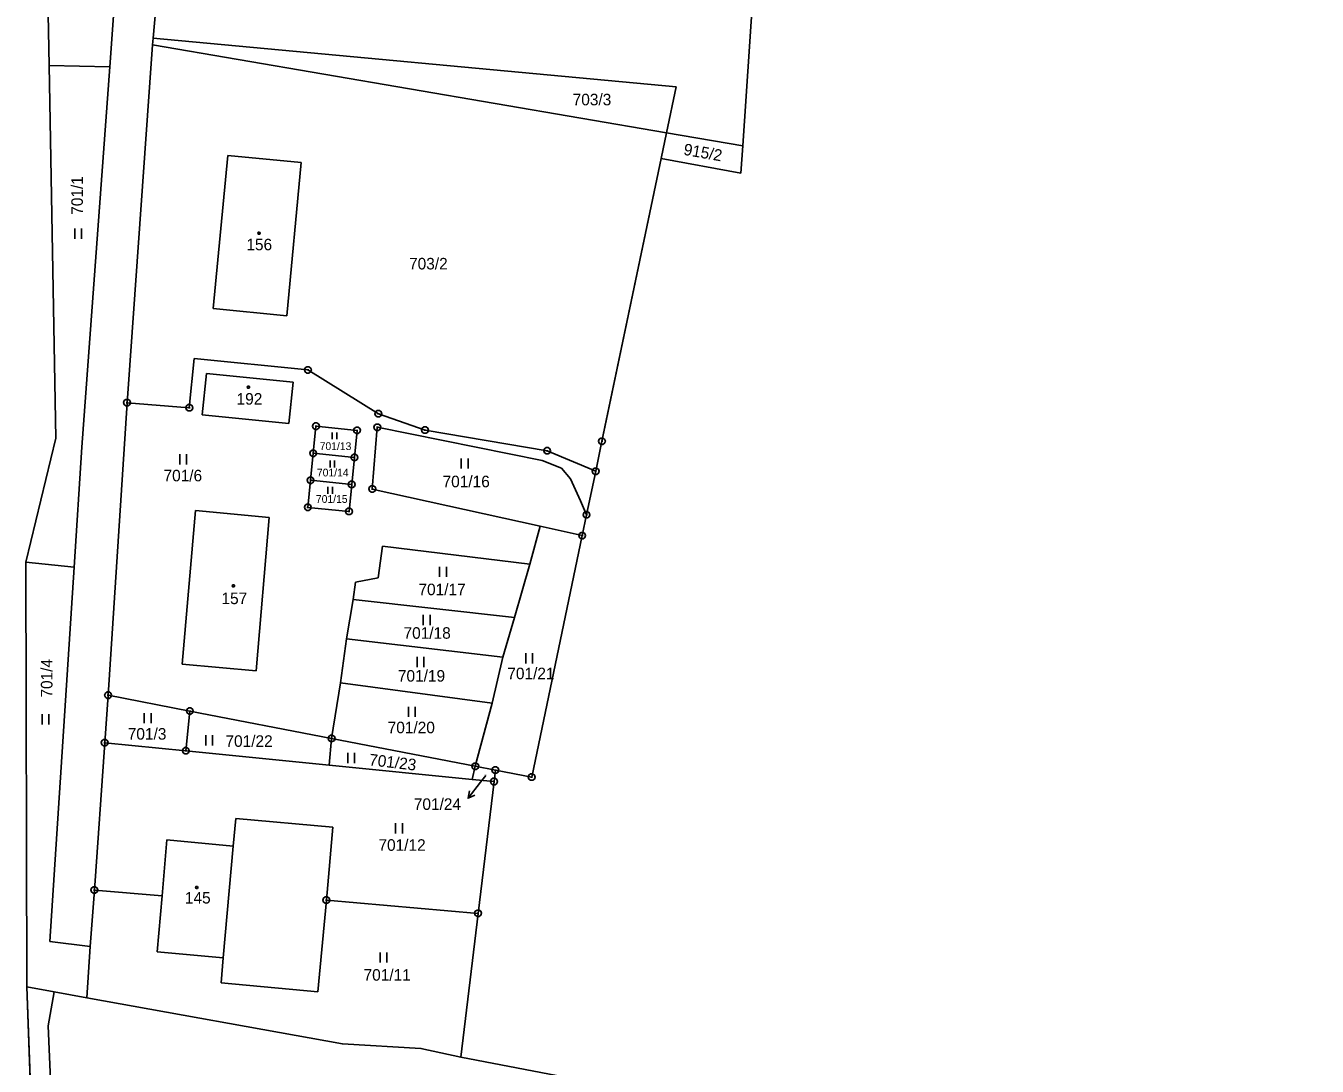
# Model space of a CAD drawing. Extents: x -580551 to -575069, y -1073031 to -1067931.
# Drawn here: x -578371.4 to -578181.2, y -1071127.8 to -1070974.7 of the extents above; entities that cross this region are included whole.
import ezdxf

# ---------------------------------------------------------------- set-up
doc = ezdxf.new("R2010")
doc.units = 0
for name, color, linetype in [('Druh pozemku', 7, 'Continuous'), ('Geodetické body', 7, 'Continuous'), ('Parcela', 7, 'Continuous'), ('Parcelní číslo', 7, 'Continuous'), ('Parcelní číslo_stavba', 7, 'Continuous'), ('Pomocná vrstva', 7, 'Continuous'), ('SR - hranice státu', 7, 'Continuous'), ('Vnitřní kresba', 7, 'Continuous')]:
    doc.layers.add(name, color=color, linetype=linetype)

msp = doc.modelspace()

# ---------------------------------------------------------------- linework, layer by layer
at = {"layer": 'Druh pozemku'}
for p, q in [((-578364.21, -1071004.53), (-578364.21, -1071006.03)), ((-578363.21, -1071006.03), (-578363.21, -1071004.53)), ((-578326.305, -1071034.525), (-578326.305, -1071035.53)), ((-578325.635, -1071035.53), (-578325.635, -1071034.525)), ((-578348.77, -1071037.74), (-578348.77, -1071039.24)), ((-578347.77, -1071039.24), (-578347.77, -1071037.74)), ((-578326.625, -1071038.685), (-578326.625, -1071039.69)), ((-578325.955, -1071039.69), (-578325.955, -1071038.685)), ((-578307.29, -1071038.36), (-578307.29, -1071039.86)), ((-578306.29, -1071039.86), (-578306.29, -1071038.36)), ((-578326.945, -1071042.545), (-578326.945, -1071043.55)), ((-578326.275, -1071043.55), (-578326.275, -1071042.545)), ((-578310.49, -1071054.3), (-578310.49, -1071055.8)), ((-578309.49, -1071055.8), (-578309.49, -1071054.3)), ((-578312.9, -1071061.4), (-578312.9, -1071062.9)), ((-578311.9, -1071062.9), (-578311.9, -1071061.4)), ((-578313.8, -1071067.57), (-578313.8, -1071069.07)), ((-578312.8, -1071069.07), (-578312.8, -1071067.57)), ((-578297.8, -1071067.03), (-578297.8, -1071068.53)), ((-578296.8, -1071068.53), (-578296.8, -1071067.03)), ((-578353.98, -1071075.84), (-578353.98, -1071077.34)), ((-578352.98, -1071077.34), (-578352.98, -1071075.84)), ((-578315.07, -1071074.9), (-578315.07, -1071076.4)), ((-578314.07, -1071076.4), (-578314.07, -1071074.9)), ((-578369.02, -1071076.02), (-578369.02, -1071077.52)), ((-578368.02, -1071077.52), (-578368.02, -1071076.02)), ((-578344.92, -1071079.1), (-578344.92, -1071080.6)), ((-578343.92, -1071080.6), (-578343.92, -1071079.1)), ((-578324.01, -1071081.7), (-578324.01, -1071083.2)), ((-578323.01, -1071083.2), (-578323.01, -1071081.7)), ((-578316.96, -1071092.04), (-578316.96, -1071093.54)), ((-578315.96, -1071093.54), (-578315.96, -1071092.04)), ((-578319.25, -1071111.07), (-578319.25, -1071112.57)), ((-578318.25, -1071112.57), (-578318.25, -1071111.07))]:
    msp.add_line(p, q, dxfattribs=at)
for points in [[(-578337, -1071005.05), (-578336.91, -1071005.2), (-578337, -1071005.35), (-578337.18, -1071005.35), (-578337.27, -1071005.2), (-578337.18, -1071005.05)], [(-578338.56, -1071027.73), (-578338.47, -1071027.88), (-578338.56, -1071028.03), (-578338.74, -1071028.03), (-578338.83, -1071027.88), (-578338.74, -1071027.73)], [(-578340.77, -1071056.98), (-578340.68, -1071057.13), (-578340.77, -1071057.28), (-578340.95, -1071057.28), (-578341.04, -1071057.13), (-578340.95, -1071056.98)], [(-578346.17, -1071101.36), (-578346.08, -1071101.51), (-578346.17, -1071101.66), (-578346.35, -1071101.66), (-578346.44, -1071101.51), (-578346.35, -1071101.36)]]:
    msp.add_lwpolyline(points, close=True, dxfattribs=at)
at = {"layer": 'Geodetické body'}
for p, q in [((-578330, -1071025.34), (-578329.76, -1071025.34)), ((-578356.64, -1071030.15), (-578356.4, -1071030.15)), ((-578347.47, -1071030.9), (-578347.23, -1071030.9)), ((-578319.62, -1071031.78), (-578319.38, -1071031.78)), ((-578328.82, -1071033.62), (-578328.58, -1071033.62)), ((-578319.78, -1071033.77), (-578319.54, -1071033.77)), ((-578322.76, -1071034.23), (-578322.52, -1071034.23)), ((-578312.75, -1071034.2), (-578312.51, -1071034.2)), ((-578286.7, -1071035.84), (-578286.46, -1071035.84)), ((-578329.22, -1071037.6), (-578328.98, -1071037.6)), ((-578294.77, -1071037.24), (-578294.53, -1071037.24)), ((-578323.15, -1071038.21), (-578322.91, -1071038.21)), ((-578329.62, -1071041.58), (-578329.38, -1071041.58)), ((-578287.62, -1071040.25), (-578287.38, -1071040.25)), ((-578323.55, -1071042.19), (-578323.31, -1071042.19)), ((-578320.52, -1071042.86), (-578320.28, -1071042.86)), ((-578330.02, -1071045.56), (-578329.78, -1071045.56)), ((-578323.95, -1071046.17), (-578323.71, -1071046.17)), ((-578288.97, -1071046.66), (-578288.73, -1071046.66)), ((-578289.6, -1071049.72), (-578289.36, -1071049.72)), ((-578359.43, -1071073.21), (-578359.19, -1071073.21)), ((-578347.38, -1071075.54), (-578347.14, -1071075.54)), ((-578326.51, -1071079.58), (-578326.27, -1071079.58)), ((-578359.93, -1071080.2), (-578359.69, -1071080.2)), ((-578347.98, -1071081.39), (-578347.74, -1071081.39)), ((-578305.35, -1071083.67), (-578305.11, -1071083.67)), ((-578302.39, -1071084.24), (-578302.15, -1071084.24)), ((-578297.04, -1071085.27), (-578296.8, -1071085.27)), ((-578302.59, -1071085.92), (-578302.35, -1071085.92)), ((-578361.46, -1071101.89), (-578361.22, -1071101.89)), ((-578327.29, -1071103.37), (-578327.05, -1071103.37)), ((-578304.94, -1071105.32), (-578304.7, -1071105.32))]:
    msp.add_line(p, q, dxfattribs=at)
for points in [[(-578329.73, -1071024.86), (-578329.48, -1071025.04), (-578329.38, -1071025.33), (-578329.48, -1071025.62), (-578329.73, -1071025.8), (-578330.04, -1071025.8), (-578330.29, -1071025.62), (-578330.39, -1071025.33), (-578330.29, -1071025.04), (-578330.04, -1071024.86)], [(-578356.37, -1071029.67), (-578356.12, -1071029.85), (-578356.02, -1071030.14), (-578356.12, -1071030.43), (-578356.37, -1071030.61), (-578356.68, -1071030.61), (-578356.93, -1071030.43), (-578357.03, -1071030.14), (-578356.93, -1071029.85), (-578356.68, -1071029.67)], [(-578347.2, -1071030.42), (-578346.95, -1071030.6), (-578346.85, -1071030.89), (-578346.95, -1071031.18), (-578347.2, -1071031.36), (-578347.51, -1071031.36), (-578347.76, -1071031.18), (-578347.86, -1071030.89), (-578347.76, -1071030.6), (-578347.51, -1071030.42)], [(-578319.35, -1071031.3), (-578319.1, -1071031.48), (-578319, -1071031.77), (-578319.1, -1071032.06), (-578319.35, -1071032.24), (-578319.66, -1071032.24), (-578319.91, -1071032.06), (-578320.01, -1071031.77), (-578319.91, -1071031.48), (-578319.66, -1071031.3)], [(-578328.55, -1071033.14), (-578328.3, -1071033.32), (-578328.2, -1071033.61), (-578328.3, -1071033.9), (-578328.55, -1071034.08), (-578328.86, -1071034.08), (-578329.11, -1071033.9), (-578329.21, -1071033.61), (-578329.11, -1071033.32), (-578328.86, -1071033.14)], [(-578322.49, -1071033.75), (-578322.24, -1071033.93), (-578322.14, -1071034.22), (-578322.24, -1071034.51), (-578322.49, -1071034.69), (-578322.8, -1071034.69), (-578323.05, -1071034.51), (-578323.15, -1071034.22), (-578323.05, -1071033.93), (-578322.8, -1071033.75)], [(-578319.51, -1071033.29), (-578319.26, -1071033.47), (-578319.16, -1071033.76), (-578319.26, -1071034.05), (-578319.51, -1071034.23), (-578319.82, -1071034.23), (-578320.07, -1071034.05), (-578320.17, -1071033.76), (-578320.07, -1071033.47), (-578319.82, -1071033.29)], [(-578312.48, -1071033.72), (-578312.23, -1071033.9), (-578312.13, -1071034.19), (-578312.23, -1071034.48), (-578312.48, -1071034.66), (-578312.79, -1071034.66), (-578313.04, -1071034.48), (-578313.14, -1071034.19), (-578313.04, -1071033.9), (-578312.79, -1071033.72)], [(-578286.43, -1071035.36), (-578286.18, -1071035.54), (-578286.08, -1071035.83), (-578286.18, -1071036.12), (-578286.43, -1071036.3), (-578286.74, -1071036.3), (-578286.99, -1071036.12), (-578287.09, -1071035.83), (-578286.99, -1071035.54), (-578286.74, -1071035.36)], [(-578328.95, -1071037.12), (-578328.7, -1071037.3), (-578328.6, -1071037.59), (-578328.7, -1071037.88), (-578328.95, -1071038.06), (-578329.26, -1071038.06), (-578329.51, -1071037.88), (-578329.61, -1071037.59), (-578329.51, -1071037.3), (-578329.26, -1071037.12)], [(-578322.88, -1071037.73), (-578322.63, -1071037.91), (-578322.53, -1071038.2), (-578322.63, -1071038.49), (-578322.88, -1071038.67), (-578323.19, -1071038.67), (-578323.44, -1071038.49), (-578323.54, -1071038.2), (-578323.44, -1071037.91), (-578323.19, -1071037.73)], [(-578294.5, -1071036.76), (-578294.25, -1071036.94), (-578294.15, -1071037.23), (-578294.25, -1071037.52), (-578294.5, -1071037.7), (-578294.81, -1071037.7), (-578295.06, -1071037.52), (-578295.16, -1071037.23), (-578295.06, -1071036.94), (-578294.81, -1071036.76)], [(-578329.35, -1071041.1), (-578329.1, -1071041.28), (-578329, -1071041.57), (-578329.1, -1071041.86), (-578329.35, -1071042.04), (-578329.66, -1071042.04), (-578329.91, -1071041.86), (-578330.01, -1071041.57), (-578329.91, -1071041.28), (-578329.66, -1071041.1)], [(-578287.35, -1071039.77), (-578287.1, -1071039.95), (-578287, -1071040.24), (-578287.1, -1071040.53), (-578287.35, -1071040.71), (-578287.66, -1071040.71), (-578287.91, -1071040.53), (-578288.01, -1071040.24), (-578287.91, -1071039.95), (-578287.66, -1071039.77)], [(-578323.28, -1071041.71), (-578323.03, -1071041.89), (-578322.93, -1071042.18), (-578323.03, -1071042.47), (-578323.28, -1071042.65), (-578323.59, -1071042.65), (-578323.84, -1071042.47), (-578323.94, -1071042.18), (-578323.84, -1071041.89), (-578323.59, -1071041.71)], [(-578320.25, -1071042.38), (-578320, -1071042.56), (-578319.9, -1071042.85), (-578320, -1071043.14), (-578320.25, -1071043.32), (-578320.56, -1071043.32), (-578320.81, -1071043.14), (-578320.91, -1071042.85), (-578320.81, -1071042.56), (-578320.56, -1071042.38)], [(-578329.75, -1071045.08), (-578329.5, -1071045.26), (-578329.4, -1071045.55), (-578329.5, -1071045.84), (-578329.75, -1071046.02), (-578330.06, -1071046.02), (-578330.31, -1071045.84), (-578330.41, -1071045.55), (-578330.31, -1071045.26), (-578330.06, -1071045.08)], [(-578323.68, -1071045.69), (-578323.43, -1071045.87), (-578323.33, -1071046.16), (-578323.43, -1071046.45), (-578323.68, -1071046.63), (-578323.99, -1071046.63), (-578324.24, -1071046.45), (-578324.34, -1071046.16), (-578324.24, -1071045.87), (-578323.99, -1071045.69)], [(-578288.7, -1071046.18), (-578288.45, -1071046.36), (-578288.35, -1071046.65), (-578288.45, -1071046.94), (-578288.7, -1071047.12), (-578289.01, -1071047.12), (-578289.26, -1071046.94), (-578289.36, -1071046.65), (-578289.26, -1071046.36), (-578289.01, -1071046.18)], [(-578289.33, -1071049.24), (-578289.08, -1071049.42), (-578288.98, -1071049.71), (-578289.08, -1071050), (-578289.33, -1071050.18), (-578289.64, -1071050.18), (-578289.89, -1071050), (-578289.99, -1071049.71), (-578289.89, -1071049.42), (-578289.64, -1071049.24)], [(-578359.16, -1071072.73), (-578358.91, -1071072.91), (-578358.81, -1071073.2), (-578358.91, -1071073.49), (-578359.16, -1071073.67), (-578359.47, -1071073.67), (-578359.72, -1071073.49), (-578359.82, -1071073.2), (-578359.72, -1071072.91), (-578359.47, -1071072.73)], [(-578347.11, -1071075.06), (-578346.86, -1071075.24), (-578346.76, -1071075.53), (-578346.86, -1071075.82), (-578347.11, -1071076), (-578347.42, -1071076), (-578347.67, -1071075.82), (-578347.77, -1071075.53), (-578347.67, -1071075.24), (-578347.42, -1071075.06)], [(-578326.24, -1071079.1), (-578325.99, -1071079.28), (-578325.89, -1071079.57), (-578325.99, -1071079.86), (-578326.24, -1071080.04), (-578326.55, -1071080.04), (-578326.8, -1071079.86), (-578326.9, -1071079.57), (-578326.8, -1071079.28), (-578326.55, -1071079.1)], [(-578359.66, -1071079.72), (-578359.41, -1071079.9), (-578359.31, -1071080.19), (-578359.41, -1071080.48), (-578359.66, -1071080.66), (-578359.97, -1071080.66), (-578360.22, -1071080.48), (-578360.32, -1071080.19), (-578360.22, -1071079.9), (-578359.97, -1071079.72)], [(-578347.71, -1071080.91), (-578347.46, -1071081.09), (-578347.36, -1071081.38), (-578347.46, -1071081.67), (-578347.71, -1071081.85), (-578348.02, -1071081.85), (-578348.27, -1071081.67), (-578348.37, -1071081.38), (-578348.27, -1071081.09), (-578348.02, -1071080.91)], [(-578305.08, -1071083.19), (-578304.83, -1071083.37), (-578304.73, -1071083.66), (-578304.83, -1071083.95), (-578305.08, -1071084.13), (-578305.39, -1071084.13), (-578305.64, -1071083.95), (-578305.74, -1071083.66), (-578305.64, -1071083.37), (-578305.39, -1071083.19)], [(-578302.12, -1071083.76), (-578301.87, -1071083.94), (-578301.77, -1071084.23), (-578301.87, -1071084.52), (-578302.12, -1071084.7), (-578302.43, -1071084.7), (-578302.68, -1071084.52), (-578302.78, -1071084.23), (-578302.68, -1071083.94), (-578302.43, -1071083.76)], [(-578296.77, -1071084.79), (-578296.52, -1071084.97), (-578296.42, -1071085.26), (-578296.52, -1071085.55), (-578296.77, -1071085.73), (-578297.08, -1071085.73), (-578297.33, -1071085.55), (-578297.43, -1071085.26), (-578297.33, -1071084.97), (-578297.08, -1071084.79)], [(-578302.32, -1071085.44), (-578302.07, -1071085.62), (-578301.97, -1071085.91), (-578302.07, -1071086.2), (-578302.32, -1071086.38), (-578302.63, -1071086.38), (-578302.88, -1071086.2), (-578302.98, -1071085.91), (-578302.88, -1071085.62), (-578302.63, -1071085.44)], [(-578361.19, -1071101.41), (-578360.94, -1071101.59), (-578360.84, -1071101.88), (-578360.94, -1071102.17), (-578361.19, -1071102.35), (-578361.5, -1071102.35), (-578361.75, -1071102.17), (-578361.85, -1071101.88), (-578361.75, -1071101.59), (-578361.5, -1071101.41)], [(-578327.02, -1071102.89), (-578326.77, -1071103.07), (-578326.67, -1071103.36), (-578326.77, -1071103.65), (-578327.02, -1071103.83), (-578327.33, -1071103.83), (-578327.58, -1071103.65), (-578327.68, -1071103.36), (-578327.58, -1071103.07), (-578327.33, -1071102.89)], [(-578304.67, -1071104.84), (-578304.42, -1071105.02), (-578304.32, -1071105.31), (-578304.42, -1071105.6), (-578304.67, -1071105.78), (-578304.98, -1071105.78), (-578305.23, -1071105.6), (-578305.33, -1071105.31), (-578305.23, -1071105.02), (-578304.98, -1071104.84)]]:
    msp.add_lwpolyline(points, close=True, dxfattribs=at)
at = {"layer": 'Parcela'}
for p, q in [((-578368.01, -1070980.5), (-578369.11, -1070918.83)), ((-578260.89, -1070918.39), (-578265.83, -1070992.35)), ((-578352.69, -1070976.5), (-578350.58, -1070952.69)), ((-578359.08, -1070980.72), (-578357.97, -1070965.53)), ((-578352.76, -1070977.5), (-578352.69, -1070976.5)), ((-578352.69, -1070976.5), (-578275.67, -1070983.67)), ((-578352.76, -1070977.5), (-578356.52, -1071030.15)), ((-578277.09, -1070990.43), (-578352.76, -1070977.5)), ((-578368.01, -1070980.5), (-578359.08, -1070980.72)), ((-578367.03, -1071035.37), (-578368.01, -1070980.5)), ((-578363.16, -1071036.7), (-578359.08, -1070980.72)), ((-578277.09, -1070990.43), (-578275.67, -1070983.67)), ((-578277.88, -1070994.21), (-578277.09, -1070990.43)), ((-578265.83, -1070992.35), (-578277.09, -1070990.43)), ((-578343.84, -1071016.3), (-578341.7, -1070993.75)), ((-578341.7, -1070993.75), (-578330.87, -1070994.78)), ((-578265.83, -1070992.35), (-578266.1, -1070996.35)), ((-578330.87, -1070994.78), (-578333, -1071017.35)), ((-578286.1, -1071033.53), (-578277.88, -1070994.21)), ((-578266.1, -1070996.35), (-578277.88, -1070994.21)), ((-578333, -1071017.35), (-578343.84, -1071016.3)), ((-578347.35, -1071030.9), (-578346.62, -1071023.66)), ((-578346.62, -1071023.66), (-578329.88, -1071025.34)), ((-578344.83, -1071025.86), (-578345.45, -1071031.94)), ((-578332.07, -1071027.13), (-578344.83, -1071025.86)), ((-578329.88, -1071025.34), (-578319.5, -1071031.78)), ((-578332.68, -1071033.22), (-578332.07, -1071027.13)), ((-578359.31, -1071073.21), (-578356.52, -1071030.15)), ((-578356.52, -1071030.15), (-578347.35, -1071030.9)), ((-578345.45, -1071031.94), (-578332.68, -1071033.22)), ((-578319.5, -1071031.78), (-578312.63, -1071034.2)), ((-578329.1, -1071037.6), (-578328.7, -1071033.62)), ((-578328.7, -1071033.62), (-578322.64, -1071034.23)), ((-578319.66, -1071033.77), (-578320.4, -1071042.86)), ((-578295.37, -1071038.67), (-578319.66, -1071033.77)), ((-578286.58, -1071035.84), (-578286.1, -1071033.53)), ((-578367.03, -1071035.37), (-578371.43, -1071053.61)), ((-578322.64, -1071034.23), (-578323.03, -1071038.21)), ((-578312.63, -1071034.2), (-578294.65, -1071037.24)), ((-578287.5, -1071040.25), (-578286.58, -1071035.84)), ((-578363.16, -1071036.7), (-578364.31, -1071054.34)), ((-578329.5, -1071041.58), (-578329.1, -1071037.6)), ((-578329.1, -1071037.6), (-578323.03, -1071038.21)), ((-578294.65, -1071037.24), (-578287.5, -1071040.25)), ((-578323.03, -1071038.21), (-578323.43, -1071042.19)), ((-578292.52, -1071039.8), (-578295.37, -1071038.67)), ((-578329.9, -1071045.56), (-578329.5, -1071041.58)), ((-578323.43, -1071042.19), (-578329.5, -1071041.58)), ((-578291.23, -1071041.38), (-578292.52, -1071039.8)), ((-578289.73, -1071044.62), (-578291.23, -1071041.38)), ((-578287.5, -1071040.25), (-578288.85, -1071046.66)), ((-578323.43, -1071042.19), (-578323.83, -1071046.17)), ((-578320.4, -1071042.86), (-578295.69, -1071048.34)), ((-578288.85, -1071046.66), (-578289.73, -1071044.62)), ((-578348.4, -1071068.64), (-578346.43, -1071046.03)), ((-578346.43, -1071046.03), (-578335.58, -1071047.07)), ((-578335.58, -1071047.07), (-578337.52, -1071069.64)), ((-578323.83, -1071046.17), (-578329.9, -1071045.56)), ((-578289.48, -1071049.72), (-578288.85, -1071046.66)), ((-578295.69, -1071048.34), (-578297.2, -1071053.9)), ((-578295.69, -1071048.34), (-578289.48, -1071049.72)), ((-578289.48, -1071049.72), (-578296.92, -1071085.27)), ((-578319.56, -1071055.94), (-578318.9, -1071051.27)), ((-578318.9, -1071051.27), (-578297.2, -1071053.9)), ((-578371.43, -1071053.61), (-578371.27, -1071116.15)), ((-578371.43, -1071053.61), (-578364.31, -1071054.34)), ((-578364.31, -1071054.34), (-578367.91, -1071109.45)), ((-578297.2, -1071053.9), (-578299.46, -1071061.76)), ((-578323.24, -1071059.12), (-578322.87, -1071056.59)), ((-578322.87, -1071056.59), (-578319.56, -1071055.94)), ((-578324.18, -1071064.89), (-578323.24, -1071059.12)), ((-578323.24, -1071059.12), (-578299.46, -1071061.76)), ((-578299.46, -1071061.76), (-578301.16, -1071067.63)), ((-578325.07, -1071071.39), (-578324.18, -1071064.89)), ((-578301.16, -1071067.63), (-578324.18, -1071064.89)), ((-578301.16, -1071067.63), (-578302.76, -1071074.38)), ((-578337.52, -1071069.64), (-578348.4, -1071068.64)), ((-578326.39, -1071079.58), (-578325.07, -1071071.39)), ((-578325.07, -1071071.39), (-578302.76, -1071074.38)), ((-578359.31, -1071073.21), (-578359.81, -1071080.2)), ((-578347.26, -1071075.54), (-578359.31, -1071073.21)), ((-578347.86, -1071081.39), (-578347.26, -1071075.54)), ((-578347.26, -1071075.54), (-578326.39, -1071079.58)), ((-578302.76, -1071074.38), (-578305.23, -1071083.67)), ((-578326.39, -1071079.58), (-578326.73, -1071083.5)), ((-578326.39, -1071079.58), (-578305.23, -1071083.67)), ((-578359.81, -1071080.2), (-578361.34, -1071101.89)), ((-578359.81, -1071080.2), (-578347.86, -1071081.39)), ((-578326.73, -1071083.5), (-578347.86, -1071081.39)), ((-578305.67, -1071085.6), (-578326.73, -1071083.5)), ((-578305.23, -1071083.67), (-578305.67, -1071085.6)), ((-578305.23, -1071083.67), (-578302.27, -1071084.24)), ((-578302.27, -1071084.24), (-578302.47, -1071085.92)), ((-578296.92, -1071085.27), (-578302.27, -1071084.24)), ((-578302.47, -1071085.92), (-578305.67, -1071085.6)), ((-578302.47, -1071085.92), (-578304.82, -1071105.32)), ((-578340.87, -1071095.42), (-578340.51, -1071091.36)), ((-578326.2, -1071092.65), (-578340.51, -1071091.36)), ((-578327.17, -1071103.37), (-578326.2, -1071092.65)), ((-578351.37, -1071102.76), (-578350.64, -1071094.51)), ((-578350.64, -1071094.51), (-578340.87, -1071095.42)), ((-578361.34, -1071101.89), (-578361.93, -1071110.21)), ((-578361.34, -1071101.89), (-578351.37, -1071102.76)), ((-578351.37, -1071102.76), (-578352.1, -1071111)), ((-578328.4, -1071116.87), (-578327.17, -1071103.37)), ((-578304.82, -1071105.32), (-578327.17, -1071103.37)), ((-578304.82, -1071105.32), (-578307.37, -1071126.48)), ((-578367.91, -1071109.45), (-578361.93, -1071110.21)), ((-578361.93, -1071110.21), (-578362.44, -1071117.74)), ((-578352.1, -1071111), (-578342.35, -1071111.88)), ((-578342.35, -1071111.88), (-578342.68, -1071115.56)), ((-578328.4, -1071116.87), (-578342.68, -1071115.56)), ((-578371.27, -1071116.15), (-578369.68, -1071161.49)), ((-578367.24, -1071116.88), (-578371.27, -1071116.15)), ((-578367.24, -1071116.88), (-578368.16, -1071121.85)), ((-578362.44, -1071117.74), (-578367.24, -1071116.88)), ((-578324.8, -1071124.54), (-578362.44, -1071117.74)), ((-578368.16, -1071121.85), (-578366.36, -1071163.55)), ((-578313.23, -1071125.19), (-578324.8, -1071124.54)), ((-578307.37, -1071126.48), (-578313.23, -1071125.19)), ((-578307.37, -1071126.48), (-578181.24, -1071150.54))]:
    msp.add_line(p, q, dxfattribs=at)
at = {"layer": 'Pomocná vrstva'}
for p in [(-578303.68, -1071085.02), (-578306.284, -1071088.384)]:
    msp.add_line(p, (-578304.45, -1071086.01), dxfattribs=at)
msp.add_lwpolyline([(-578305.277, -1071087.899), (-578306.284, -1071088.384), (-578306.068, -1071087.287)], dxfattribs=at)
at = {"layer": 'SR - hranice státu'}
msp.add_line((-578371.27, -1071116.15), (-578367.24, -1071116.88), dxfattribs=at)
for points in [[(-578277.88, -1070994.21), (-578277.09, -1070990.43), (-578352.76, -1070977.5), (-578352.69, -1070976.5), (-578350.58, -1070952.69), (-578343.88, -1070891.64), (-578313.16, -1070902.82), (-578289.65, -1070910.64)], [(-578289.48, -1071049.72), (-578288.85, -1071046.66), (-578287.5, -1071040.25), (-578286.58, -1071035.84), (-578277.88, -1070994.21)], [(-578307.37, -1071126.48), (-578304.82, -1071105.32), (-578302.47, -1071085.92), (-578302.27, -1071084.24), (-578296.92, -1071085.27), (-578289.48, -1071049.72)], [(-578371.27, -1071116.15), (-578369.68, -1071161.49), (-578367.78, -1071172.91)], [(-578367.24, -1071116.88), (-578362.44, -1071117.74), (-578324.8, -1071124.54), (-578313.23, -1071125.19), (-578307.37, -1071126.48)]]:
    msp.add_lwpolyline(points, dxfattribs=at)
at = {"layer": 'Vnitřní kresba'}
msp.add_line((-578340.87, -1071095.42), (-578342.35, -1071111.88), dxfattribs=at)

# ---------------------------------------------------------------- texts
at = {"layer": 'Parcelní číslo'}
for s, height, p in [('703/3', 1.7, (-578290.891, -1070986.38)), ('703/2', 1.7, (-578314.989, -1071010.54)), ('701/13', 1.14, (-578328.149, -1071037.12)), ('701/6', 1.7, (-578351.15, -1071041.73)), ('701/14', 1.14, (-578328.558, -1071041.01)), ('701/16', 1.7, (-578310.051, -1071042.6)), ('701/15', 1.14, (-578328.705, -1071044.9)), ('701/17', 1.7, (-578313.606, -1071058.49)), ('701/18', 1.7, (-578315.799, -1071064.9)), ('701/19', 1.7, (-578316.631, -1071071.21)), ('701/21', 1.7, (-578300.516, -1071070.86)), ('701/20', 1.7, (-578318.137, -1071078.81)), ('701/3', 1.7, (-578356.417, -1071079.75)), ('701/22', 1.7, (-578342.029, -1071080.81)), ('701/24', 0.1, (-578303.906, -1071085.02)), ('701/12', 1.7, (-578319.496, -1071096.11)), ('701/11', 1.7, (-578321.684, -1071115.23))]:
    msp.add_text(s, height=height, dxfattribs=at).set_placement(p)
for s, rotation, p in [('915/2', 350.07721, (-578274.646, -1070993.653)), ('701/1', 90.01167, (-578363.03, -1071002.493)), ('701/4', 90.01167, (-578367.509, -1071073.56)), ('701/23', 353.34307, (-578320.937, -1071083.509))]:
    msp.add_text(s, height=1.7, rotation=rotation, dxfattribs=at).set_placement(p)
at = {"layer": 'Parcelní číslo_stavba'}
for s, p in [('156', (-578338.949, -1071007.72)), ('192', (-578340.392, -1071030.44)), ('157', (-578342.613, -1071059.8)), ('145', (-578347.999, -1071103.87))]:
    msp.add_text(s, height=1.7, dxfattribs=at).set_placement(p)
at = {"layer": 'Pomocná vrstva'}
msp.add_text('701/24', height=1.7, dxfattribs=at).set_placement((-578314.285, -1071090.09))

doc.saveas('drawing.dxf')
